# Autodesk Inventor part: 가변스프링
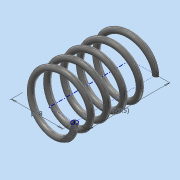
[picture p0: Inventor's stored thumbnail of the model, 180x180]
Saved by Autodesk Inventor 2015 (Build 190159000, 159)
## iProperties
Created: 2017-12
Part Number: 가변스프링
Material: 스테인레스 스틸
Document SubType Name: Modeling
Designer: SCD-A03
Density: 8 g/cm^3
Appearance: 반연마
Mass: 6.99592 g
Surface Area: 17.7531 cm^2
Volume: 0.87449 cm^3
Author: SCD-A03
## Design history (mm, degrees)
sketch "스케치1"
  geometry: L1 (0, 0)-(9, 0); L2 (9, 0)-(9, 28.5); L3 (9, 28.5)-(0, 28.5); L4 (0, 28.5)-(0, 0); C1 r 1 at (9, 0)
  constraints: 8 end point, 2 parallel, 1 centre point, 1 coincident, 1 horizontal, 1 perpendicular
  dimensions: "d1" = 2 diameter of C1; "d3" = 18 diameter of L2 L4; "d5" = 28.5 distance of L1.end L2.end (derived)
feature "코일1" pitch "d6" = 10; turns "d8" = 5; dims "d7" = 28.5 (= d5), "d9" = 0, angle "d10" = 90 deg, angle "d11" = 90 deg, "d12" = 0, "d13" = 0
sketch "스케치2"
  geometry: L1 (-10, 0)-(-8, 0) reference; 1 further point
  constraints: 1 horizontal alignment
extrude "돌출1" cut sketch "스케치2" stored distance "d14" = 10; taper "d15" = 0 deg
node "작업 평면1"
sketch "스케치3"
  geometry: L1 (1, 0)-(-1, 0) reference; 1 further point
  constraints: 1 horizontal alignment
extrude "돌출2" cut sketch "스케치3" stored distance "d17" = 10; taper "d18" = 0 deg
node "솔리드1"
node "절단 모서리 투영1"
node "절단 모서리 투영2"
other parameters: "d16" = 90 deg
